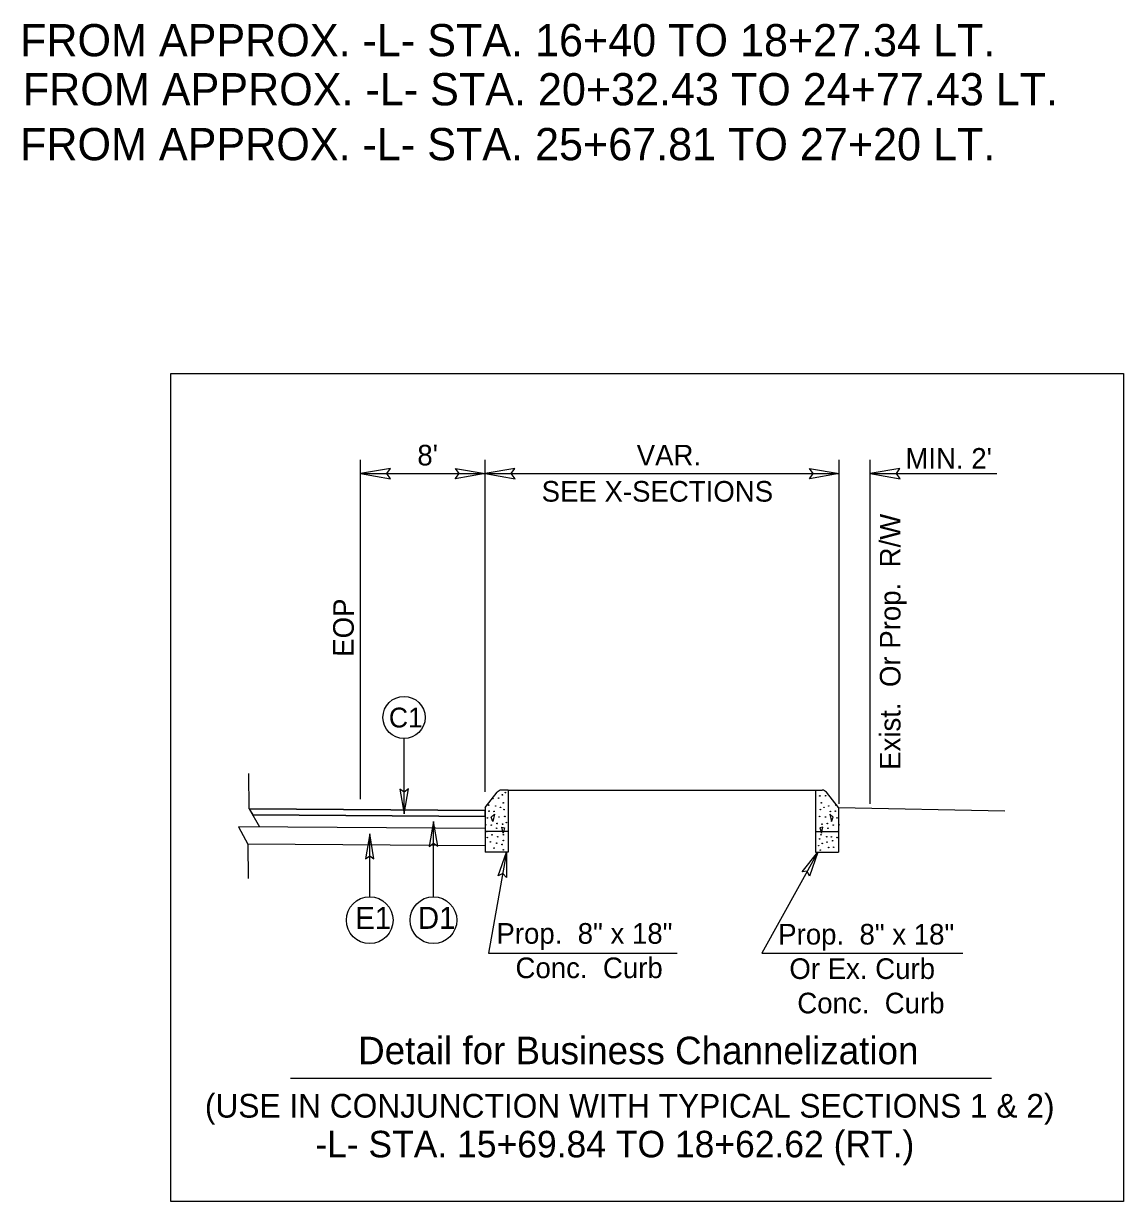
# Model space of a CAD drawing. Extents: x 981824 to 982276, y 44828 to 45204.
# Drawn here: x 982246.65 to 982272.24, y 45127.92 to 45155.31 of the extents above; entities that cross this region are included whole.
import ezdxf

# ---------------------------------------------------------------- set-up
doc = ezdxf.new("R2010")
doc.units = 0
for name, color, linetype in [('Old_Level_1', 7, 'Continuous'), ('Old_Level_11', 7, 'Continuous'), ('Old_Level_17', 7, 'Continuous'), ('Old_Level_2', 7, 'Continuous'), ('Old_Level_3', 7, 'Continuous'), ('Old_Level_6', 7, 'Continuous'), ('Old_Level_7', 7, 'Continuous'), ('Old_Level_9', 7, 'Continuous'), ('Prop Conc Curb 8in x 12in', 7, 'Continuous'), ('Prop Dimension Text', 7, 'Continuous'), ('Typical Curb CELL', 7, 'Continuous'), ('Typical Terminator CELL', 7, 'Continuous')]:
    doc.layers.add(name, color=color, linetype=linetype)

msp = doc.modelspace()

# ---------------------------------------------------------------- linework, layer by layer
at = {"layer": 'Old_Level_1'}
for p, q in [((982254.492, 45137.277), (982254.492, 45145.166)), ((982257.388, 45137.445), (982257.388, 45145.166)), ((982265.626, 45137.168), (982265.626, 45145.166)), ((982266.346, 45137.168), (982266.346, 45145.166)), ((982254.492, 45144.846), (982257.388, 45144.846)), ((982257.388, 45144.846), (982265.626, 45144.846)), ((982266.346, 45144.846), (982269.287, 45144.846)), ((982257.922, 45137.485), (982265.075, 45137.485)), ((982265.608, 45137.085), (982269.473, 45137.007)), ((982257.888, 45136.043), (982257.469, 45133.695)), ((982265.128, 45136.045), (982263.822, 45133.695)), ((982257.469, 45133.695), (982261.857, 45133.695)), ((982263.822, 45133.695), (982268.499, 45133.695))]:
    msp.add_line(p, q, dxfattribs=at)
at = {"layer": 'Old_Level_11'}
for points in [[(982257.689, 45135.494), (982257.888, 45136.043), (982257.887, 45135.455), (982257.799, 45135.546)], [(982264.761, 45135.59), (982265.128, 45136.045), (982264.936, 45135.489), (982264.882, 45135.603)]]:
    msp.add_lwpolyline(points, close=True, dxfattribs=at)
at = {"layer": 'Old_Level_17'}
for p, q in [((982257.388, 45137.013), (982251.9, 45137.054)), ((982251.9, 45137.054), (982251.981, 45136.909)), ((982251.981, 45136.909), (982257.388, 45136.869)), ((982257.388, 45136.869), (982257.388, 45137.013))]:
    msp.add_line(p, q, dxfattribs=at)
msp.add_lwpolyline([(982250.08, 45147.172), (982272.236, 45147.172), (982272.236, 45127.922), (982250.08, 45127.922)], close=True, dxfattribs=at)
at = {"layer": 'Old_Level_2'}
for p, q in [((982251.9, 45137.054), (982251.891, 45137.874)), ((982251.9, 45137.054), (982252.136, 45136.63)), ((982251.9, 45137.054), (982257.388, 45137.013)), ((982257.388, 45136.869), (982251.981, 45136.909)), ((982257.388, 45136.59), (982251.648, 45136.633)), ((982251.648, 45136.633), (982251.867, 45136.233)), ((982257.388, 45136.341), (982257.388, 45136.192)), ((982257.388, 45136.192), (982251.867, 45136.233)), ((982251.867, 45136.233), (982251.874, 45135.431))]:
    msp.add_line(p, q, dxfattribs=at)
at = {"layer": 'Old_Level_6'}
for p, q in [((982255.501, 45136.935), (982255.501, 45138.687)), ((982256.185, 45135.005), (982256.185, 45136.757)), ((982254.703, 45135.005), (982254.703, 45136.467))]:
    msp.add_line(p, q, dxfattribs=at)
for centre, radius in [((982255.501, 45139.176), 0.49), ((982254.703, 45134.461), 0.544), ((982256.185, 45134.461), 0.544)]:
    msp.add_circle(centre, radius, dxfattribs=at)
at = {"layer": 'Old_Level_9'}
msp.add_line((982252.862, 45130.792), (982269.169, 45130.792), dxfattribs=at)
at = {"layer": 'Prop Conc Curb 8in x 12in'}
for p, q in [((982257.53, 45136.861), (982257.605, 45136.928)), ((982257.567, 45136.757), (982257.53, 45136.861)), ((982257.605, 45136.928), (982257.567, 45136.757)), ((982265.409, 45136.928), (982265.447, 45136.757)), ((982265.485, 45136.861), (982265.409, 45136.928)), ((982265.447, 45136.757), (982265.485, 45136.861)), ((982257.773, 45136.628), (982257.84, 45136.612)), ((982257.806, 45136.487), (982257.773, 45136.628)), ((982257.84, 45136.612), (982257.806, 45136.487)), ((982265.241, 45136.628), (982265.175, 45136.612)), ((982265.175, 45136.612), (982265.208, 45136.487)), ((982265.208, 45136.487), (982265.241, 45136.628))]:
    msp.add_line(p, q, dxfattribs=at)
for centre in [(982257.791, 45137.377), (982257.86, 45137.428), (982265.173, 45137.351), (982265.306, 45137.356), (982257.468, 45137.137), (982257.572, 45137.288), (982257.633, 45137.117), (982257.701, 45137.302), (982257.745, 45137.086), (982257.808, 45137.19), (982265.207, 45137.19), (982265.269, 45137.086), (982265.382, 45137.117), (982265.546, 45137.137), (982257.442, 45136.84), (982257.481, 45136.996), (982257.597, 45136.991), (982257.709, 45136.861), (982257.829, 45137.034), (982257.846, 45136.876), (982265.168, 45136.876), (982265.186, 45137.034), (982265.305, 45136.861), (982265.418, 45136.991), (982265.534, 45136.996), (982265.572, 45136.84), (982257.397, 45136.678), (982257.426, 45136.522), (982257.53, 45136.673), (982257.655, 45136.6), (982257.667, 45136.71), (982257.792, 45136.694), (982257.881, 45136.732), (982265.222, 45136.694), (982265.347, 45136.71), (982265.36, 45136.6), (982265.485, 45136.673), (982265.589, 45136.522), (982265.618, 45136.678), (982257.438, 45136.382), (982257.509, 45136.281), (982257.548, 45136.447), (982257.657, 45136.252), (982257.68, 45136.402), (982257.81, 45136.314), (982257.813, 45136.449), (982265.166, 45136.351), (982265.201, 45136.449), (982265.229, 45136.247), (982265.335, 45136.402), (982265.341, 45136.278), (982265.442, 45136.397), (982265.468, 45136.31), (982265.576, 45136.382), (982257.597, 45136.138), (982257.782, 45136.223), (982257.81, 45136.099), (982265.145, 45136.195), (982265.183, 45136.093), (982265.377, 45136.152), (982265.493, 45136.158)]:
    msp.add_ellipse(centre, major_axis=(0, -0.00731), ratio=0.8, dxfattribs=at)
at = {"layer": 'Typical Curb CELL'}
for p, q in [((982257.388, 45137.085), (982257.671, 45137.436)), ((982257.922, 45137.485), (982257.767, 45137.485)), ((982257.922, 45137.485), (982257.922, 45136.525)), ((982265.075, 45137.485), (982265.229, 45137.485)), ((982265.075, 45137.485), (982265.075, 45136.525)), ((982265.608, 45137.085), (982265.325, 45137.436)), ((982257.388, 45137.085), (982257.388, 45136.525)), ((982265.608, 45137.085), (982265.608, 45136.525)), ((982257.388, 45136.53), (982257.388, 45136.045)), ((982257.922, 45136.53), (982257.922, 45136.045)), ((982265.075, 45136.53), (982265.075, 45136.045)), ((982265.608, 45136.53), (982265.608, 45136.045)), ((982257.922, 45136.525), (982257.388, 45136.525)), ((982265.075, 45136.525), (982265.608, 45136.525)), ((982257.922, 45136.045), (982257.388, 45136.045)), ((982265.075, 45136.045), (982265.608, 45136.045))]:
    msp.add_line(p, q, dxfattribs=at)
for centre, start_param, end_param in [((982257.767, 45137.325), 0, 0.802857), ((982265.229, 45137.325), 5.480329, 6.283185)]:
    msp.add_ellipse(centre, major_axis=(0, 0.16), ratio=0.833333, start_param=start_param, end_param=end_param, dxfattribs=at)
at = {"layer": 'Typical Terminator CELL'}
for points in [[(982255.183, 45144.965), (982254.492, 45144.846), (982255.187, 45144.723), (982255.098, 45144.846)], [(982256.697, 45144.965), (982257.388, 45144.846), (982256.693, 45144.723), (982256.782, 45144.846)], [(982258.08, 45144.965), (982257.388, 45144.846), (982258.083, 45144.723), (982257.995, 45144.846)], [(982264.935, 45144.965), (982265.626, 45144.846), (982264.931, 45144.723), (982265.019, 45144.846)], [(982267.037, 45144.965), (982266.346, 45144.846), (982267.041, 45144.723), (982266.953, 45144.846)], [(982255.402, 45137.511), (982255.501, 45136.935), (982255.604, 45137.514), (982255.501, 45137.441)], [(982256.284, 45136.181), (982256.185, 45136.757), (982256.083, 45136.178), (982256.185, 45136.251)], [(982254.802, 45135.891), (982254.703, 45136.467), (982254.601, 45135.888), (982254.703, 45135.961)]]:
    msp.add_lwpolyline(points, close=True, dxfattribs=at)

# ---------------------------------------------------------------- texts
at = {"layer": 'Old_Level_1'}
for s, p in [("8'", (982255.811, 45145.036)), ('VAR.', (982260.913, 45145.035)), ("MIN. 2'", (982267.163, 45144.96)), ('SEE X-SECTIONS', (982258.701, 45144.194)), ('Prop.  8" x 18"', (982257.65, 45133.914)), ('Prop.  8" x 18"', (982264.205, 45133.895)), ('Conc.  Curb', (982258.094, 45133.114)), ('Or Ex. Curb', (982264.464, 45133.095)), ('Conc.  Curb', (982264.649, 45132.295))]:
    msp.add_text(s, height=0.48, dxfattribs=at).set_placement(p)
for s, rotation, p in [('Exist.  Or Prop.  R/W', 90, (982267.049, 45137.957)), ('EOP', 89.6557, (982254.328, 45140.585))]:
    msp.add_text(s, height=0.48, rotation=rotation, dxfattribs=at).set_placement(p)
at = {"layer": 'Old_Level_17'}
msp.add_text('Detail for Business Channelization', height=0.64, dxfattribs=at).set_placement((982254.433, 45131.112))
at = {"layer": 'Old_Level_3'}
for s, height, p in [('(USE IN CONJUNCTION WITH TYPICAL SECTIONS 1 & 2)', 0.55074, (982250.869, 45129.871)), ('-L- STA. 15+69.84 TO 18+62.62 (RT.)', 0.61669, (982253.437, 45128.947))]:
    msp.add_text(s, height=height, dxfattribs=at).set_placement(p)
at = {"layer": 'Old_Level_7'}
for s, height, p in [('C1', 0.4608, (982255.149, 45138.943)), ('E1', 0.512, (982254.365, 45134.258)), ('D1', 0.512, (982255.822, 45134.26))]:
    msp.add_text(s, height=height, dxfattribs=at).set_placement(p)
at = {"layer": 'Prop Dimension Text'}
for s, p in [('FROM APPROX. -L- STA. 16+40 TO 18+27.34 LT.', (982246.568, 45154.55)), ('FROM APPROX. -L- STA. 20+32.43 TO 24+77.43 LT.', (982246.635, 45153.409)), ('FROM APPROX. -L- STA. 25+67.81 TO 27+20 LT.', (982246.568, 45152.133))]:
    msp.add_text(s, height=0.75, dxfattribs=at).set_placement(p)

doc.saveas('drawing.dxf')
